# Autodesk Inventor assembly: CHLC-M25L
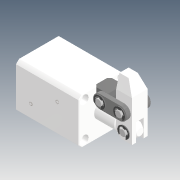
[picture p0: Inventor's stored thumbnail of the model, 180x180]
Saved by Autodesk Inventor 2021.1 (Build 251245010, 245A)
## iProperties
Company: Microsoft
Created: 2019-11
Part Number: CHLC-M25L
Description: STEP AP214
Document SubType Name: Assembly
Designer: user
Title: CHLC-M25L.STEP
Author: Windows
Revision Number: ÈÎºÎ
Sending System: SolidWorks 2015
Preprocessor: SwSTEP 2.0
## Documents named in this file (10)
- D:\Vault_2016\Projekty\Clamptek\Hydraulic\CHLC\CHLC-25\Inventor\CHLC-M25L\CHLC-M25L.iam
- D:\Vault_2016\Projekty\Clamptek\Hydraulic\CHLC\CHLC-25\Inventor\CHLC-M25L\CHLC-25ZC.ipt
- D:\Vault_2016\Projekty\Clamptek\Hydraulic\CHLC\CHLC-25\Inventor\CHLC-M25L\CHLC-25LG.ipt
- D:\Vault_2016\Projekty\Clamptek\Hydraulic\CHLC\CHLC-25\Inventor\CHLC-M25L\CHLC-25HSG.ipt
- D:\Vault_2016\Projekty\Clamptek\Hydraulic\CHLC\CHLC-25\Inventor\CHLC-M25L\CHLC-25DX.ipt
- D:\Vault_2016\Projekty\Clamptek\Hydraulic\CHLC\CHLC-25\Inventor\CHLC-M25L\CHLC-25CX.ipt
- D:\Vault_2016\Projekty\Clamptek\Hydraulic\CHLC\CHLC-25\Inventor\CHLC-M25L\CHLC-25KKDC.ipt
- D:\Vault_2016\Projekty\Clamptek\Hydraulic\CHLC\CHLC-25\Inventor\CHLC-M25L\chlc-m25bt_1.ipt
- D:\Vault_2016\Projekty\Clamptek\Hydraulic\CHLC\CHLC-25\Inventor\CHLC-M25L\socket set screw cup point_iso_ISO 4029 - M5 x 6-N.ipt
- D:\Vault_2016\Projekty\Clamptek\Hydraulic\CHLC\CHLC-25\Inventor\CHLC-M25L\Ñ¹±Û.ipt
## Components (17 placed, 17 different names)
1. CHLC-25ZC_1
2. CHLC-25LG_2
3. CHLC-25LG_3
4. CHLC-25HSG_4
5. CHLC-25DX_5
6. CHLC-25CX_6
7. CHLC-25CX_7
8. CHLC-25KKDC_8
9. CHLC-25KKDC_9
10. CHLC-25KKDC_10
11. CHLC-25KKDC_11
12. CHLC-25KKDC_12
13. CHLC-25KKDC_13
14. chlc-m25bt_1_14
15. socket set screw cup point_iso_ISO 4029 - M5 x 6-N_15
16. socket set screw cup point_iso_ISO 4029 - M5 x 6-N_16
17. Ñ¹±Û_17
